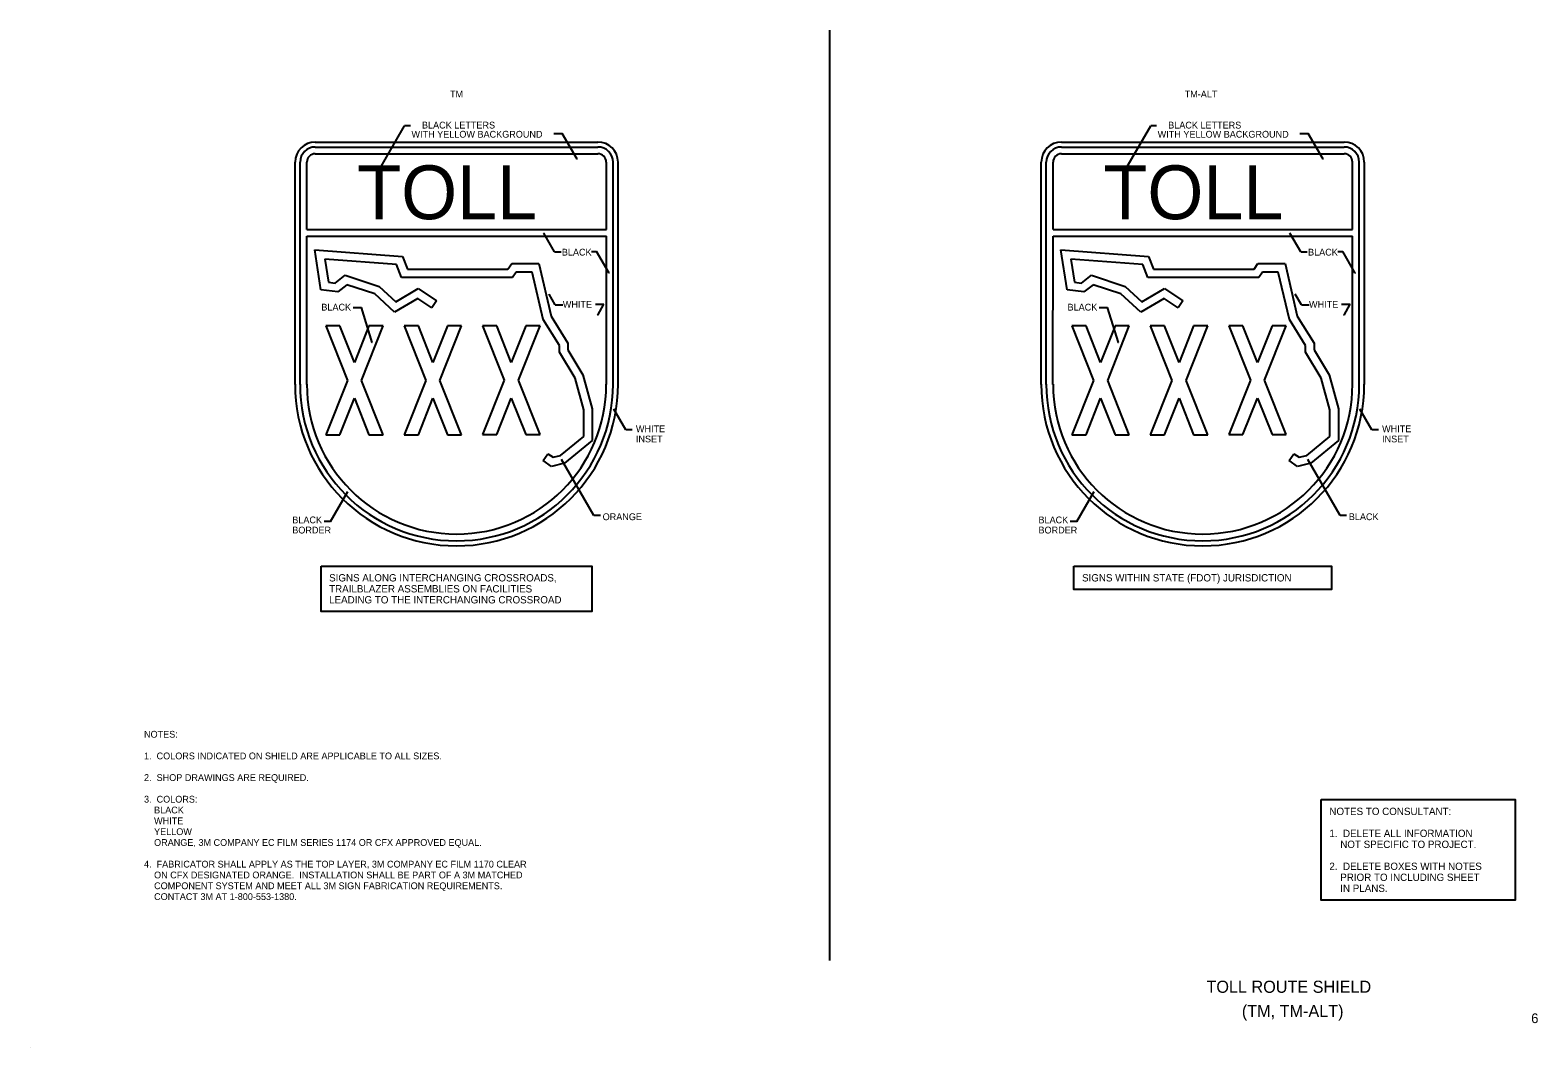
# Model space of a CAD drawing. Extents: x 52204 to 54071, y 10312 to 11572.
import ezdxf

# ---------------------------------------------------------------- set-up
doc = ezdxf.new("R2010")
doc.units = 0
for name, color, linetype in [('AdhocPoint_dp', 7, 'Continuous'), ('Default', 7, 'Continuous'), ('GSDims', 7, 'Continuous'), ('NonPlottingEle_dp', 7, 'Continuous'), ('SignPanel', 7, 'Continuous'), ('TextAlert', 7, 'Continuous'), ('TextMisc', 7, 'Continuous'), ('TextNotes', 7, 'Continuous'), ('TextShtNo', 7, 'Continuous')]:
    doc.layers.add(name, color=color, linetype=linetype)

msp = doc.modelspace()

# ---------------------------------------------------------------- linework, layer by layer
at = {"layer": 'AdhocPoint_dp'}
msp.add_line((52204.2, 10312.4), (52204.2, 10312.4), dxfattribs=at)
at = {"layer": 'GSDims'}
for p, q in [((52634.2, 11395.8), (52667.9, 11454)), ((52675.1, 11454), (52667.9, 11454)), ((52852.7, 11444.4), (52863.1, 11444.4)), ((52881.4, 11412.8), (52863.1, 11444.4)), ((53558.2, 11395.8), (53591.9, 11454)), ((53599.1, 11454), (53591.9, 11454)), ((53776.5, 11444.4), (53786.9, 11444.4)), ((53805.2, 11412.8), (53786.9, 11444.4)), ((52853.5, 11297.9), (52840.1, 11321.1)), ((53777.5, 11297.9), (53764.1, 11321.1)), ((52853.5, 11297.9), (52861.6, 11297.9)), ((52899.3, 11298.3), (52905.5, 11298.3)), ((52921, 11271.5), (52905.5, 11298.3)), ((53777.5, 11297.9), (53785.6, 11297.9)), ((53823.3, 11298.3), (53829.5, 11298.3)), ((53845, 11271.5), (53829.5, 11298.3)), ((52854.4, 11232.5), (52846.8, 11245.6)), ((53778.4, 11232.5), (53770.8, 11245.6)), ((52604, 11228.9), (52614.4, 11228.9)), ((52627.8, 11185.7), (52614.4, 11228.9)), ((52854.4, 11232.5), (52864, 11232.5)), ((52904.2, 11233.3), (52914.7, 11233.3)), ((52907.3, 11219.6), (52914.7, 11233.3)), ((53528, 11228.9), (53538.4, 11228.9)), ((53551.8, 11185.7), (53538.4, 11228.9)), ((53778.4, 11232.5), (53788, 11232.5)), ((53828.2, 11233.3), (53838.7, 11233.3)), ((53831.3, 11219.6), (53838.7, 11233.3)), ((52941.7, 11077.4), (52926.8, 11103.3)), ((53865.7, 11077.4), (53850.8, 11103.3)), ((52949.8, 11077.4), (52941.7, 11077.4)), ((53873.8, 11077.4), (53865.7, 11077.4)), ((52902.4, 10971.4), (52862.3, 11040.9)), ((53826.4, 10971.4), (53786.3, 11040.9)), ((52576.2, 10963.9), (52597.7, 11001.1)), ((53500.2, 10963.9), (53521.8, 11001.1)), ((52576.2, 10963.9), (52568.1, 10963.9)), ((52910.4, 10971.4), (52902.4, 10971.4)), ((53500.2, 10963.9), (53492.2, 10963.9)), ((53834.4, 10971.4), (53826.4, 10971.4))]:
    msp.add_line(p, q, dxfattribs=at)
at = {"layer": 'NonPlottingEle_dp'}
msp.add_line((53194.2, 11572.4), (53194.2, 10420.4), dxfattribs=at)
at = {"layer": 'SignPanel'}
for p, q in [((52557.3, 11433.9), (52907.2, 11433.9)), ((52557.3, 11427.6), (52907.2, 11427.6)), ((53481.3, 11433.9), (53831.2, 11433.9)), ((53481.3, 11427.6), (53831.2, 11427.6)), ((52532.2, 11133.8), (52532.3, 11408.9)), ((52538.4, 11133.8), (52538.5, 11408.9)), ((52546.8, 11325.5), (52546.8, 11408.9)), ((52557.3, 11419.3), (52907.2, 11419.3)), ((52917.8, 11325.5), (52917.8, 11408.9)), ((52926.1, 11133.8), (52926.1, 11408.9)), ((52932.3, 11133.8), (52932.3, 11408.9)), ((53456.2, 11133.8), (53456.3, 11408.9)), ((53462.4, 11133.8), (53462.5, 11408.9)), ((53470.8, 11325.5), (53470.8, 11408.9)), ((53481.3, 11419.3), (53831.2, 11419.3)), ((53841.8, 11325.5), (53841.8, 11408.9)), ((53850.1, 11133.8), (53850.1, 11408.9)), ((53856.3, 11133.8), (53856.3, 11408.9)), ((52546.7, 11133.8), (52546.8, 11317.2)), ((52546.8, 11325.5), (52599, 11325.5)), ((52546.8, 11317.2), (52917.8, 11317.2)), ((52599, 11325.5), (52917.8, 11325.5)), ((52917.8, 11133.8), (52917.8, 11317.2)), ((53470.7, 11133.8), (53470.8, 11317.2)), ((53470.8, 11325.5), (53523, 11325.5)), ((53470.8, 11317.2), (53841.8, 11317.2)), ((53523, 11325.5), (53841.8, 11325.5)), ((53841.8, 11133.8), (53841.8, 11317.2)), ((52556.6, 11300.5), (52665.2, 11292.1)), ((52564.3, 11250.8), (52556.6, 11300.5)), ((53480.6, 11300.5), (53589.2, 11292.1)), ((53488.3, 11250.8), (53480.6, 11300.5)), ((52657.9, 11282.2), (52569, 11289)), ((52569, 11289), (52573.5, 11260.2)), ((52664.1, 11266), (52657.9, 11282.2)), ((52665.2, 11292.1), (52671.3, 11276.5)), ((52671.3, 11276.5), (52795.9, 11276.5)), ((52795.9, 11276.5), (52800.6, 11283.4)), ((52800.6, 11283.4), (52834.2, 11283.4)), ((52834.2, 11283.4), (52849.3, 11218.1)), ((53581.9, 11282.2), (53493, 11289)), ((53493, 11289), (53497.5, 11260.2)), ((53588.2, 11266), (53581.9, 11282.2)), ((53589.2, 11292.1), (53595.3, 11276.5)), ((53595.3, 11276.5), (53719.9, 11276.5)), ((53719.9, 11276.5), (53724.6, 11283.4)), ((53724.6, 11283.4), (53758.2, 11283.4)), ((53758.2, 11283.4), (53773.3, 11218.1)), ((52573.5, 11260.2), (52582.1, 11259.1)), ((52582.1, 11259.1), (52594.4, 11268.9)), ((52594.4, 11268.9), (52636.3, 11255.2)), ((52801.5, 11266), (52664.1, 11266)), ((52806.2, 11272.9), (52801.5, 11266)), ((52825.8, 11272.9), (52806.2, 11272.9)), ((52839.5, 11214), (52825.8, 11272.9)), ((53497.5, 11260.2), (53506.1, 11259.1)), ((53506.1, 11259.1), (53518.4, 11268.9)), ((53518.4, 11268.9), (53560.3, 11255.2)), ((53725.5, 11266), (53588.2, 11266)), ((53730.2, 11272.9), (53725.5, 11266)), ((53749.8, 11272.9), (53730.2, 11272.9)), ((53763.5, 11214), (53749.8, 11272.9)), ((52585.1, 11248.2), (52564.3, 11250.8)), ((52596.5, 11257.2), (52585.1, 11248.2)), ((52630.9, 11246), (52596.5, 11257.2)), ((52655.5, 11223.2), (52630.9, 11246)), ((52636.3, 11255.2), (52656.9, 11236.2)), ((52684.4, 11240.2), (52655.5, 11223.2)), ((52656.9, 11236.2), (52684.8, 11252.6)), ((52701.6, 11228.5), (52684.4, 11240.2)), ((52684.8, 11252.6), (52707.5, 11237.2)), ((53509.1, 11248.2), (53488.3, 11250.8)), ((53520.5, 11257.2), (53509.1, 11248.2)), ((53554.9, 11246), (53520.5, 11257.2)), ((53579.5, 11223.2), (53554.9, 11246)), ((53560.3, 11255.2), (53580.9, 11236.2)), ((53608.4, 11240.2), (53579.5, 11223.2)), ((53580.9, 11236.2), (53608.8, 11252.6)), ((53625.6, 11228.5), (53608.4, 11240.2)), ((53608.8, 11252.6), (53631.5, 11237.2)), ((52707.5, 11237.2), (52701.6, 11228.5)), ((53631.5, 11237.2), (53625.6, 11228.5)), ((52587.8, 11206.1), (52570.2, 11206.1)), ((52570.2, 11206.1), (52597, 11138.7)), ((52605.7, 11160.8), (52587.8, 11206.1)), ((52623.7, 11206.1), (52605.7, 11160.8)), ((52614.5, 11138.7), (52641.3, 11206.1)), ((52641.3, 11206.1), (52623.7, 11206.1)), ((52684.9, 11206.2), (52667.3, 11206.2)), ((52667.3, 11206.2), (52694.1, 11138.8)), ((52702.9, 11160.9), (52684.9, 11206.2)), ((52720.9, 11206.2), (52702.9, 11160.9)), ((52711.7, 11138.8), (52738.4, 11206.2)), ((52738.4, 11206.2), (52720.9, 11206.2)), ((52782, 11206.3), (52764.5, 11206.3)), ((52764.5, 11206.3), (52791.2, 11138.9)), ((52800, 11161), (52782, 11206.3)), ((52818, 11206.3), (52800, 11161)), ((52808.8, 11138.9), (52835.6, 11206.3)), ((52835.6, 11206.3), (52818, 11206.3)), ((52859.5, 11181.9), (52839.5, 11214)), ((52849.3, 11218.1), (52870, 11184.9)), ((53511.8, 11206.1), (53494.2, 11206.1)), ((53494.2, 11206.1), (53521, 11138.7)), ((53529.7, 11160.8), (53511.8, 11206.1)), ((53547.7, 11206.1), (53529.7, 11160.8)), ((53538.5, 11138.7), (53565.3, 11206.1)), ((53565.3, 11206.1), (53547.7, 11206.1)), ((53608.9, 11206.2), (53591.3, 11206.2)), ((53591.3, 11206.2), (53618.1, 11138.8)), ((53626.9, 11160.9), (53608.9, 11206.2)), ((53644.9, 11206.2), (53626.9, 11160.9)), ((53635.7, 11138.8), (53662.4, 11206.2)), ((53662.4, 11206.2), (53644.9, 11206.2)), ((53706, 11206.3), (53688.5, 11206.3)), ((53688.5, 11206.3), (53715.2, 11138.9)), ((53724, 11161), (53706, 11206.3)), ((53742, 11206.3), (53724, 11161)), ((53732.8, 11138.9), (53759.6, 11206.3)), ((53759.6, 11206.3), (53742, 11206.3)), ((53783.5, 11181.9), (53763.5, 11214)), ((53773.3, 11218.1), (53794, 11184.9)), ((52870, 11184.9), (52870, 11176.5)), ((53794, 11184.9), (53794, 11176.5)), ((52859.5, 11173.6), (52859.5, 11181.9)), ((52879, 11141.5), (52859.5, 11173.6)), ((52870, 11176.5), (52888.7, 11145.7)), ((53783.5, 11173.6), (53783.5, 11181.9)), ((53803, 11141.5), (53783.5, 11173.6)), ((53794, 11176.5), (53812.7, 11145.7)), ((52888.7, 11145.7), (52900.2, 11103.6)), ((53812.7, 11145.7), (53824.2, 11103.6)), ((52597, 11138.7), (52570.2, 11071.4)), ((52641.3, 11071.4), (52614.5, 11138.7)), ((52694.1, 11138.8), (52667.3, 11071.5)), ((52738.4, 11071.5), (52711.7, 11138.8)), ((52791.2, 11138.9), (52764.5, 11071.6)), ((52835.6, 11071.6), (52808.8, 11138.9)), ((52889.7, 11102.2), (52879, 11141.5)), ((53521, 11138.7), (53494.2, 11071.4)), ((53565.3, 11071.4), (53538.5, 11138.7)), ((53618.1, 11138.8), (53591.3, 11071.5)), ((53662.4, 11071.5), (53635.7, 11138.8)), ((53715.2, 11138.9), (53688.5, 11071.6)), ((53759.6, 11071.6), (53732.8, 11138.9)), ((53813.7, 11102.2), (53803, 11141.5)), ((52587.8, 11071.4), (52605.7, 11116.6)), ((52605.7, 11116.6), (52623.7, 11071.4)), ((52684.9, 11071.5), (52702.9, 11116.7)), ((52702.9, 11116.7), (52720.9, 11071.5)), ((52782, 11071.6), (52800, 11116.9)), ((52800, 11116.9), (52818, 11071.6)), ((53511.8, 11071.4), (53529.8, 11116.6)), ((53529.8, 11116.6), (53547.7, 11071.4)), ((53608.9, 11071.5), (53626.9, 11116.7)), ((53626.9, 11116.7), (53644.9, 11071.5)), ((53706, 11071.6), (53724, 11116.9)), ((53724, 11116.9), (53742, 11071.6)), ((52889.7, 11069.2), (52889.7, 11102.2)), ((52900.2, 11103.6), (52900.2, 11064.3)), ((53813.7, 11069.2), (53813.7, 11102.2)), ((53824.2, 11103.6), (53824.2, 11064.3)), ((52570.2, 11071.4), (52587.8, 11071.4)), ((52623.7, 11071.4), (52641.3, 11071.4)), ((52667.3, 11071.5), (52684.9, 11071.5)), ((52720.9, 11071.5), (52738.4, 11071.5)), ((52764.5, 11071.6), (52782, 11071.6)), ((52818, 11071.6), (52835.6, 11071.6)), ((53494.2, 11071.4), (53511.8, 11071.4)), ((53547.7, 11071.4), (53565.3, 11071.4)), ((53591.3, 11071.5), (53608.9, 11071.5)), ((53644.9, 11071.5), (53662.4, 11071.5)), ((53688.5, 11071.6), (53706, 11071.6)), ((53742, 11071.6), (53759.6, 11071.6)), ((52861.1, 11045.8), (52889.7, 11069.2)), ((52900.2, 11064.3), (52865.9, 11036.1)), ((53785.1, 11045.8), (53813.7, 11069.2)), ((53824.2, 11064.3), (53789.9, 11036.1)), ((52839.3, 11039.4), (52845.2, 11048)), ((52849.6, 11032.2), (52839.3, 11039.4)), ((52845.2, 11048), (52851.7, 11043.5)), ((52865.9, 11036.1), (52849.6, 11032.2)), ((52851.7, 11043.5), (52861.1, 11045.8)), ((53763.3, 11039.4), (53769.2, 11048)), ((53773.6, 11032.2), (53763.3, 11039.4)), ((53769.2, 11048), (53775.7, 11043.5)), ((53789.9, 11036.1), (53773.6, 11032.2)), ((53775.7, 11043.5), (53785.1, 11045.8))]:
    msp.add_line(p, q, dxfattribs=at)
for centre, radius, start, end in [((52557.3, 11408.9), 25, 90, 179.9792), ((52557.3, 11408.9), 18.8, 90, 179.9792), ((52907.2, 11408.9), 25, 0, 90), ((52907.2, 11408.9), 18.8, 0, 90), ((53481.3, 11408.9), 25, 90, 179.9792), ((53481.3, 11408.9), 18.8, 90, 179.9792), ((53831.2, 11408.9), 25, 0, 90), ((53831.2, 11408.9), 18.8, 0, 90), ((52557.3, 11408.9), 10.4, 90, 179.9792), ((52907.2, 11408.9), 10.4, 0, 90), ((53481.3, 11408.9), 10.4, 90, 179.9792), ((53831.2, 11408.9), 10.4, 0, 90), ((52732.2, 11133.9), 200, 180, 0), ((52732.2, 11133.9), 193.8, 180, 0), ((52732.2, 11133.9), 185.4, 180, 0), ((53656.2, 11133.9), 200, 180, 0), ((53656.2, 11133.9), 193.8, 180, 0), ((53656.2, 11133.9), 185.4, 180, 0)]:
    msp.add_arc(centre, radius, start, end, dxfattribs=at)
at = {"layer": 'TextAlert'}
for points in [[(52564.4, 10908.9), (52899.9, 10908.9), (52899.9, 10852.6), (52564.4, 10852.6)], [(53496.7, 10908.9), (53815.6, 10908.9), (53815.6, 10879.8), (53496.7, 10879.8)], [(53803, 10619.7), (54043.2, 10619.7), (54043.2, 10495.4), (53803, 10495.4)]]:
    msp.add_lwpolyline(points, close=True, dxfattribs=at)

# ---------------------------------------------------------------- texts
at = {"layer": 'Default'}
for s, p in [('TM', (52724.1, 11489)), ('TM-ALT', (53633.8, 11489))]:
    msp.add_text(s, height=8.4, dxfattribs=at).set_placement(p)
at = {"layer": 'GSDims'}
for s, p in [('WITH YELLOW BACKGROUND', (52676.4, 11439.3)), ('BLACK LETTERS', (52689.4, 11450.6)), ('WITH YELLOW BACKGROUND', (53600.4, 11439.3)), ('BLACK LETTERS', (53613.4, 11450.6)), ('.', (52632.7, 11395.1)), ('.', (53556.7, 11395.1)), ('BLACK', (52862.6, 11293.3)), ('BLACK', (53786.6, 11293.3)), ('.', (52845, 11244.5)), ('.', (53769, 11244.5)), ('BLACK', (52564.8, 11225.2)), ('WHITE', (52863.8, 11228.7)), ('BLACK', (53488.8, 11225.2)), ('WHITE', (53787.8, 11228.7)), ('.', (52626, 11184.6)), ('.', (53550, 11184.6)), ('.', (52925, 11102.1)), ('.', (53849, 11102.1)), ('WHITE', (52954.3, 11074.6)), ('WHITE', (53878.3, 11074.6)), ('INSET', (52954.3, 11062)), ('INSET', (53878.3, 11062)), ('.', (52860.5, 11039.6)), ('.', (53784.5, 11039.6)), ('.', (52595.9, 10999.8)), ('.', (53519.9, 10999.8)), ('BLACK', (52528.8, 10961.8)), ('ORANGE', (52913.1, 10965.7)), ('BLACK', (53452.8, 10961.8)), ('BLACK', (53837.1, 10965.7)), ('BORDER', (52528.8, 10949.2)), ('BORDER', (53452.8, 10949.2))]:
    msp.add_text(s, height=8.4, dxfattribs=at).set_placement(p)
for rotation, p in [(90, (52882.2, 11410.8)), (90, (53806.1, 11410.8)), (90, (52841.1, 11319.5)), (90, (53765.1, 11319.5)), (301.5608, (52905.4, 11220.5)), (301.5608, (53829.4, 11220.5))]:
    msp.add_text('.', height=8.4, rotation=rotation, dxfattribs=at).set_placement(p)
at = {"layer": 'SignPanel'}
for p in [(52609.2, 11338.3), (53533.2, 11338.3)]:
    msp.add_text('TOLL', height=66.65, dxfattribs=at).set_placement(p)
for p in [(52922, 11270), (53846, 11270)]:
    msp.add_text('.', height=7.2, rotation=90, dxfattribs=at).set_placement(p)
at = {"layer": 'TextAlert'}
for s, p in [('TRAILBLAZER ASSEMBLIES ON FACILITIES', (52574.4, 10876.2)), ('SIGNS ALONG INTERCHANGING CROSSROADS,', (52574.4, 10889.8)), ('SIGNS WITHIN STATE (FDOT) JURISDICTION', (53506.7, 10889.8)), ('LEADING TO THE INTERCHANGING CROSSROAD', (52574.4, 10862.6)), ('NOTES TO CONSULTANT:', (53813, 10600.6)), ('1.  DELETE ALL INFORMATION', (53813, 10573.4)), ('    NOT SPECIFIC TO PROJECT.', (53813, 10559.8)), ('2.  DELETE BOXES WITH NOTES', (53813, 10532.6)), ('    PRIOR TO INCLUDING SHEET', (53813, 10519)), ('    IN PLANS.', (53813, 10505.4))]:
    msp.add_text(s, height=9.072, dxfattribs=at).set_placement(p)
at = {"layer": 'TextMisc'}
for s, p in [('   TOLL ROUTE SHIELD    ', (53644.1, 10380.5)), ('      (TM, TM-ALT)      ', (53671.2, 10350.5))]:
    msp.add_text(s, height=15, rotation=360, dxfattribs=at).set_placement(p)
at = {"layer": 'TextNotes'}
for s, p in [('NOTES:', (52345.2, 10696.4)), ('1.  COLORS INDICATED ON SHIELD ARE APPLICABLE TO ALL SIZES.', (52345.2, 10669.6)), ('2.  SHOP DRAWINGS ARE REQUIRED.', (52345.2, 10642.8)), ('3.  COLORS:', (52345.2, 10616)), ('    BLACK', (52345.2, 10602.6)), ('    WHITE', (52345.2, 10589.2)), ('    YELLOW', (52345.2, 10575.8)), ('    ORANGE, 3M COMPANY EC FILM SERIES 1174 OR CFX APPROVED EQUAL.', (52345.2, 10562.4)), ('4.  FABRICATOR SHALL APPLY AS THE TOP LAYER, 3M COMPANY EC FILM 1170 CLEAR', (52345.2, 10535.6)), ('    ON CFX DESIGNATED ORANGE.  INSTALLATION SHALL BE PART OF A 3M MATCHED', (52345.2, 10522.2)), ('    COMPONENT SYSTEM AND MEET ALL 3M SIGN FABRICATION REQUIREMENTS.', (52345.2, 10508.8)), ('    CONTACT 3M AT 1-800-553-1380.', (52345.2, 10495.4))]:
    msp.add_text(s, height=8.4, dxfattribs=at).set_placement(p)
at = {"layer": 'TextShtNo'}
msp.add_text('  6  ', height=12, rotation=360, dxfattribs=at).set_placement((54054, 10343))

doc.saveas('drawing.dxf')
